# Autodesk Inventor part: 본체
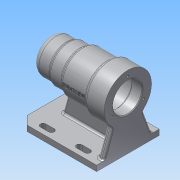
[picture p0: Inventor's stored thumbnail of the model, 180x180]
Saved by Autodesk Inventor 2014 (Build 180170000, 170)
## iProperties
Created: 2017-09
Part Number: 본체
Material: 알루미늄 6061
Document SubType Name: Modeling
Designer: user
Density: 2.71 g/cm^3
Appearance: 알루미늄 - 평지
Mass: 700.2 g
Surface Area: 709.663 cm^2
Volume: 258.376 cm^3
Author: user
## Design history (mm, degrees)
sketch "스케치1"
  geometry: L1 (56, 45)-(-56, 45); L2 (-56, 45)-(-56, -45); L3 (-56, -45)-(56, -45); L4 (56, -45)-(56, 45); L5 (56, 45)-(-56, -45); L6 (-56, 45)-(56, -45); 1 further point
  constraints: 12 end point, 2 midpoint, 2 parallel, 1 horizontal, 1 perpendicular
  dimensions: "d0" = 112 distance of L2.end L3.end; "d1" = 90 distance of L1.end L2.end
extrude "돌출1" new body sketch "스케치1" distance "d2" = 8; taper "d3" = 0 deg
sketch "스케치2"
  geometry: C1 r 34 at (45, 70); 1 further point
  constraints: 1 centre point, 1 vertical alignment
  dimensions: "d4" = 70 distance of point (45, 0) C1.centre; "d5" = 68 diameter of C1
extrude "돌출2" join sketch "스케치2" distance "d6" = 28; taper "d7" = 0 deg
sketch "스케치3"
  geometry: C1 r 34 at (0, 0) reference; C2 r 30 at (0, 0); 1 further point
  constraints: 1 centre point, 1 coincident
  dimensions: "d8" = 60 diameter of C2
extrude "돌출3" join sketch "스케치3" distance "d9" = 39; taper "d10" = 0 deg
sketch "스케치4"
  geometry: C1 r 30 at (0, 0) reference; C2 r 27 at (0, 0); 1 further point
  constraints: 1 centre point, 1 coincident
  dimensions: "d11" = 54 diameter of C2
extrude "돌출4" join sketch "스케치4" distance "d12" = 20; taper "d13" = 0 deg
sketch "스케치5"
  geometry: C1 r 27 at (0, 0) reference; C2 r 25 at (0, 0); 1 further point
  constraints: 1 centre point, 1 coincident
  dimensions: "d14" = 50 diameter of C2
extrude "돌출5" join sketch "스케치5" distance "d15" = 25; taper "d16" = 0 deg
chamfer "모따기1" distance "d17" = 12; stored, may be unused: second distance "d18" = 2, angle "d19" = 45 deg
fillet "모깎기1" dims "d20" = 3
fillet "모깎기2" dims "d21" = 9
sketch "스케치6"
  geometry: C1 r 34 at (0, 0) reference; C2 r 21 at (0, 0); 1 further point
  constraints: 1 centre point, 1 coincident
  dimensions: "d22" = 42 diameter of C2
extrude "돌출6" cut sketch "스케치6" distance "d23" = 15; taper "d24" = 0 deg
sketch "스케치7"
  geometry: C1 r 21 at (0, 0) reference; C2 r 24 at (0, 0); 1 further point
  constraints: 1 centre point, 1 coincident
  dimensions: "d25" = 48 diameter of C2
extrude "돌출7" cut sketch "스케치7" distance "d26" = 54; taper "d27" = 0 deg
sketch "스케치8"
  geometry: C1 r 21 at (0, 0) reference; C2 r 21 at (0, 0); 1 further point
  constraints: 1 centre point, 1 coincident
  dimensions: "d28" = 42 diameter of C2
extrude "돌출8" cut sketch "스케치8" distance "d29" = 12; taper "d30" = 0 deg
sketch "스케치9"
  geometry: C1 r 21 at (0, 0) reference; C2 r 17.5 at (0, 0); 1 further point
  constraints: 1 centre point, 1 coincident
  dimensions: "d31" = 35 diameter of C2
extrude "돌출9" cut sketch "스케치9" distance "d32" = 18; taper "d33" = 0 deg
sketch "스케치10"
  geometry: C1 r 25 at (0, 0) reference; C2 r 16 at (0, 0); 1 further point
  constraints: 1 centre point, 1 coincident
  dimensions: "d34" = 32 diameter of C2
extrude "돌출10" cut sketch "스케치10" distance "d35" = 4; taper "d36" = 0 deg
sketch "스케치11"
  geometry: C1 r 16 at (0, 0) reference; C2 r 10.5 at (0, 0); 1 further point
  constraints: 1 centre point, 1 coincident
  dimensions: "d37" = 21 diameter of C2
extrude "돌출11" cut sketch "스케치11" distance "d38" = 3; taper "d39" = 0 deg
fillet "모깎기3" dims "d40" = 3
chamfer "모따기2" distance "d41" = 1; stored, may be unused: second distance "d42" = 2, angle "d43" = 45 deg; dims "d16" = 0
sketch "스케치12"
  geometry: L1 (0, 26)-(0, 0); L2 (0, 0)-(-22.517, -13); C1 r 34 at (0, 0) reference; A1 r 26 centre (0, 0) between (0, 26) and (-22.517, -13); 3 further points
  constraints: 4 end point, 2 coincident, 2 point on circle, 1 centre point, 1 symmetric about line, 1 vertical, 1 vertical alignment
  dimensions: "d44" = 52 diameter of A1; "d45" = 120 deg angle of L1 L2
hole "구멍1" sketch "스케치12" at (0, 26), (-22.517, -13), (22.517, -13) diameter "d46" = 3.242; stored, may be unused: countersink angle "d50" = 90 deg, drill point angle "d52" = 118 deg; dims "d47" = 8, "d48" = 4, "d49" = 2, "d51" = 11
sketch "스케치13"
  geometry: L1 (-32, -34)-(-20, -34); L2 (-32, -38)-(-20, -38); L3 (-20, -30)-(-32, -30); L4 (20, -34)-(32, -34); L5 (20, -38)-(32, -38); L6 (32, -30)-(20, -30); L7 (56, -45)-(56, 45) reference; L8 (0, 0)-(-17.114, 0); L9 (20, 34)-(32, 34); L10 (20, 38)-(32, 38); L11 (32, 30)-(20, 30); L12 (-32, 34)-(-20, 34); L13 (-32, 38)-(-20, 38); L14 (-20, 30)-(-32, 30); A1 r 4 centre (-32, -34) between (-32, -30) and (-32, -38); A2 r 4 centre (-20, -34) between (-20, -38) and (-20, -30); A3 r 4 centre (20, -34) between (20, -30) and (20, -38); A4 r 4 centre (32, -34) between (32, -38) and (32, -30); A5 r 4 centre (32, 34) between (32, 30) and (32, 38); A6 r 4 centre (20, 34) between (20, 38) and (20, 30); A7 r 4 centre (-32, 34) between (-32, 38) and (-32, 30); A8 r 4 centre (-20, 34) between (-20, 30) and (-20, 38); 4 further points
  constraints: 34 end point, 16 point on circle, 14 symmetric about line, 8 centre point, 8 tangent, 4 point on line, 2 midpoint, 2 parallel, 1 horizontal, 1 perpendicular, 4 other
  dimensions: "d53" = 12 distance of L4.end L4.start; "d54" = 34 vertical distance of L8.start point (26, -34); "d56" = 24 distance from line of L4.end L7; "d57" = 40 distance of L1.end L4.start; "d58" = 12 distance of L1.end L1.start; "d91" = 4 radius of A2; "d92" = 4 radius of A4
extrude "돌출12" cut sketch "스케치13" stored distance "d59" = 3; taper "d60" = 0 deg
sketch "스케치14"
  geometry: L1 (0, 8)-(12, 8) reference; L2 (78, 8)-(90, 8) reference; L3 (78, 8)-(12, 8) reference; L4 (0, 0)-(0, 8) reference; L5 (90, 8)-(90, 0) reference; L6 (80, 8)-(66.9, 43.992); L7 (10, 8)-(23.1, 43.992); L8 (10, 8)-(80, 8); A1 r 34 centre (45, 70) between (66.9, 43.992) and (23.1, 43.992) reference; A2 r 34 centre (45, 70) between (23.1, 43.992) and (66.9, 43.992); 1 further point
  constraints: 6 end point, 4 point on circle, 2 point on line, 1 centre point, 1 coincident, 1 collinear, 1 concentric
  dimensions: "d62" = 10 distance from line of L5 L6.start; "d63" = 110 deg angle of L2 L6; "d64" = 10 distance from line of L4 L7.start; "d65" = 110 deg angle of L1 L7
extrude "돌출13" join sketch "스케치14" distance "d66" = 8; taper "d67" = 0 deg
sketch "스케치16"
  geometry: L1 (-56, 54)-(-56, 86) reference; L2 (-47, 95)-(-32.644, 95) reference; L3 (-28.172, 97)-(-13.196, 97) reference; L4 (-8, 100)-(25.343, 100) reference; L5 (31, 104)-(56, 104) reference; L6 (56, 104)-(56, 97.621) reference; L7 (56, 97.621)-(45, 97.621) reference; L8 (45, 97.621)-(44.026, 96) reference; L9 (44.026, 96)-(45, 94.379) reference; L10 (45, 94.379)-(56, 94.379) reference; L11 (56, 94.379)-(56, 92) reference; L12 (56, 92)-(55, 91) reference; L13 (55, 91)-(41, 91) reference; L14 (38, 94)-(-10, 94) reference; L15 (-13, 91)-(-25, 91) reference; L16 (-25, 91)-(-25, 87.5) reference; L17 (-25, 87.5)-(-43, 87.5) reference; L18 (-43, 87.5)-(-43, 86) reference; L19 (-43, 86)-(-47, 86) reference; L20 (-47, 86)-(-47, 80.5) reference; L21 (-50, 77.5)-(-50, 62.5) reference; L22 (-47, 59.5)-(-47, 54) reference; L23 (-47, 54)-(-43, 54) reference; L24 (-43, 54)-(-43, 52.5) reference; L25 (-43, 52.5)-(-25, 52.5) reference; L26 (-25, 52.5)-(-25, 49) reference; L27 (-25, 49)-(-13, 49) reference; L28 (-10, 46)-(38, 46) reference; L29 (41, 49)-(55, 49) reference; L30 (55, 49)-(56, 48) reference; L31 (56, 48)-(56, 0) reference; L32 (56, 0)-(-56, 0) reference; L33 (-56, 0)-(-56, 8) reference; L34 (-56, 8)-(48, 8) reference; L35 (48, 8)-(48, 36) reference; L36 (48, 36)-(31, 36) reference; L37 (25.343, 40)-(-8, 40) reference; L38 (-13.196, 43)-(-28.172, 43) reference; L39 (-32.644, 45)-(-47, 45) reference; L40 (-34, 8)-(-24.089, 44.988); L41 (-34, 8)-(51.518, 8); L42 (51.518, 8)-(51.518, 44.988); L43 (-24.089, 44.988)-(51.518, 44.988); A1 r 9 centre (-47, 54) between (-56, 54) and (-47, 45) reference; A2 r 9 centre (-47, 86) between (-47, 95) and (-56, 86) reference; A3 r 3 centre (-32.644, 98) between (-32.644, 95) and (-30.408, 96) reference; A4 r 3 centre (-28.172, 94) between (-28.172, 97) and (-30.408, 96) reference; A5 r 3 centre (-13.196, 100) between (-13.196, 97) and (-10.598, 98.5) reference; A6 r 3 centre (-8, 97) between (-8, 100) and (-10.598, 98.5) reference; A7 r 3 centre (31, 101) between (31, 104) and (28.172, 102) reference; A8 r 3 centre (38, 91) between (41, 91) and (38, 94) reference; A9 r 3 centre (-10, 91) between (-10, 94) and (-13, 91) reference; A10 r 3 centre (-47, 77.5) between (-47, 80.5) and (-50, 77.5) reference; A11 r 3 centre (-47, 62.5) between (-50, 62.5) and (-47, 59.5) reference; A12 r 3 centre (-10, 49) between (-13, 49) and (-10, 46) reference; A13 r 3 centre (38, 49) between (38, 46) and (41, 49) reference; A14 r 3 centre (31, 39) between (28.172, 38) and (31, 36) reference; A15 r 3 centre (-8, 43) between (-10.598, 41.5) and (-8, 40) reference; A16 r 3 centre (-13.196, 40) between (-10.598, 41.5) and (-13.196, 43) reference; A17 r 3 centre (-28.172, 46) between (-30.408, 44) and (-28.172, 43) reference; A18 r 3 centre (-32.644, 42) between (-30.408, 44) and (-32.644, 45) reference; 1 further point
  constraints: 8 end point, 2 perpendicular, 2 point on line, 2 other
  dimensions: "d74" = 22 distance from line of L33 L40.start; "d76" = 105 deg angle of L34 L40
extrude "돌출15" join sketch "스케치16" stored distance "d77" = 8; taper "d78" = 0 deg
fillet "모깎기4" dims "d79" = 3
fillet "모깎기5" dims "d80" = 3
fillet "모깎기6" dims "d81" = 3
node "작업 평면3"
sketch "스케치18"
  geometry: L1 (28, -70)-(-72, -70) reference; L2 (28, -22)-(28, 22) reference; 2 further points
  constraints: 1 other
  dimensions: "d86" = 70 distance from line of L1 point (-20, 0); "d87" = 48 distance from line of L2 point (-20, 0)
feature "엠보싱2" sketch "스케치18" dims "d0" = 112, "d1" = 90, "d88" = 0.5, "d89" = 0
fillet "모깎기7" dims "d90" = 0.3
node "솔리드1"
node "절단 모서리 투영2"
other parameters: "d70" = 105 deg
